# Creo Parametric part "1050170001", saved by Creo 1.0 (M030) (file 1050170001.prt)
Units: millimeter Newton Second (mmNs); MM, TONNE, SECS

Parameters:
  DESCRIPTION = "MICRO USB BOTTOM MOUNT RECEPTACLE, B TYPE"
  MATERIAL = "LCP, BLACK, UL94V-0"
  SERIES_NO = "105017"
  REVISION = "F"
  DOCUMENT_CONTROL = "SD-105017-001"

Other parameters: NO_OF_CKTS

Other named items: FLANGE, BACK_COVER, SIDE, TOP, FRONT, CSYS

Layers: 1_ALL_PLANES, 1__DEF_PRT_PLN, 2_ALL_CSYS, 2__DEF_PRT_CSYS, 5_ALL_CURVES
